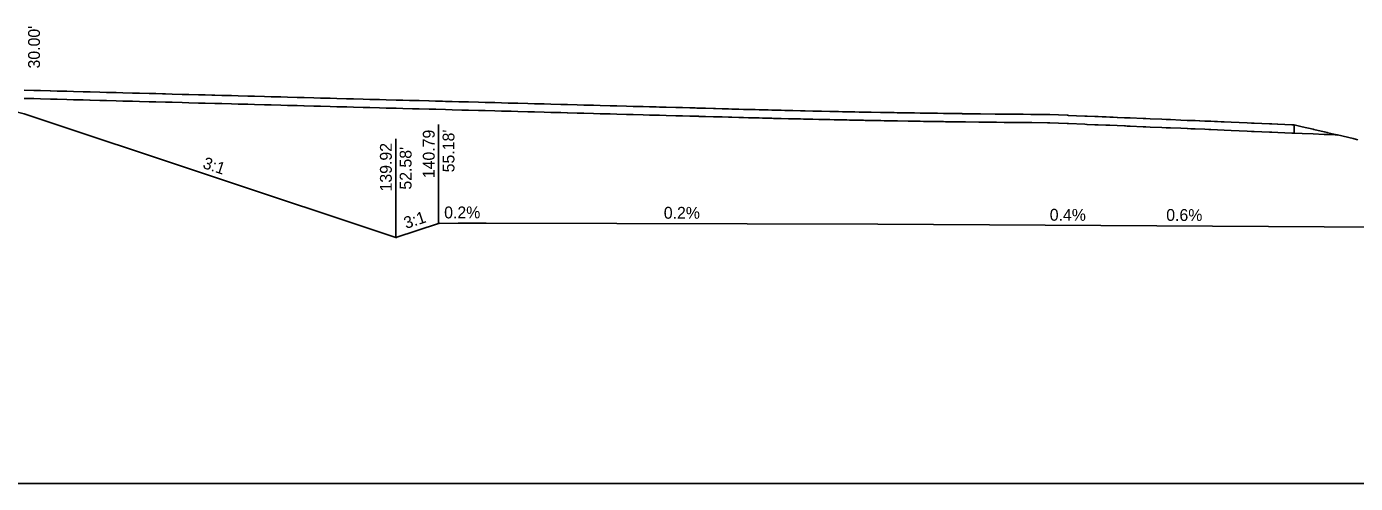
# Model space of a CAD drawing. Extents: x -26 to 4403, y -13 to 9578.
# Drawn here: x 1280.1 to 1360.9, y 8000 to 8027.7 of the extents above; entities that cross this region are included whole.
import ezdxf

# ---------------------------------------------------------------- set-up
doc = ezdxf.new("R2010")
doc.units = 0
for name, color, linetype in [('CONST_DCH', 7, 'Continuous'), ('CONST_LV3', 7, 'Continuous'), ('DTM_CORRIDOR', 7, 'Continuous'), ('DTM_P_FINISHED_GRADE', 7, 'Continuous'), ('DTM_X_GROUND', 7, 'Continuous'), ('XS_CELL', 7, 'Continuous'), ('XS_P_DR_GRAVEL', 7, 'Continuous'), ('XS_P_GROUND', 7, 'Continuous'), ('XS_P_TX_CLEARZONE', 7, 'Continuous'), ('XS_P_TX_FS_BS', 7, 'Continuous')]:
    doc.layers.add(name, color=color, linetype=linetype)

msp = doc.modelspace()

# ---------------------------------------------------------------- linework, layer by layer
at = {"layer": 'CONST_LV3'}
msp.add_lwpolyline([(1280.004, 8023.88), (1280.591, 8023.864), (1281, 8023.854), (1281.59, 8023.838), (1282, 8023.827), (1282.41, 8023.816), (1283, 8023.8), (1283.59, 8023.785), (1284, 8023.774), (1284.59, 8023.758), (1285, 8023.747), (1285.41, 8023.736), (1286, 8023.721), (1286.591, 8023.705), (1287, 8023.694), (1287.591, 8023.679), (1288, 8023.668), (1288.409, 8023.657), (1289, 8023.641), (1289.591, 8023.625), (1290, 8023.615), (1290.591, 8023.599), (1291, 8023.588), (1291.408, 8023.577), (1292, 8023.561), (1292.592, 8023.546), (1293, 8023.535), (1293.592, 8023.519), (1294, 8023.508), (1294.592, 8023.493), (1295, 8023.482), (1295.593, 8023.466), (1296, 8023.455), (1296.593, 8023.439), (1297, 8023.429), (1297.593, 8023.413), (1298, 8023.402), (1298.407, 8023.391), (1299, 8023.375), (1299.593, 8023.36), (1300, 8023.349), (1300.594, 8023.333), (1301, 8023.322), (1301.406, 8023.311), (1302, 8023.296), (1302.594, 8023.28), (1303, 8023.269), (1303.406, 8023.258), (1304, 8023.243), (1304.594, 8023.227), (1305, 8023.216), (1305.406, 8023.205), (1306, 8023.189), (1306.405, 8023.179), (1307, 8023.163), (1307.595, 8023.147), (1308, 8023.136), (1308.595, 8023.121), (1309, 8023.11), (1309.405, 8023.099), (1310, 8023.083), (1310.596, 8023.067), (1311, 8023.057), (1311.404, 8023.046), (1312, 8023.03), (1312.596, 8023.014), (1313, 8023.004), (1313.596, 8022.988), (1314, 8022.977), (1314.404, 8022.966), (1315, 8022.95), (1315.597, 8022.935), (1316, 8022.924), (1316.597, 8022.908), (1317, 8022.897), (1317.403, 8022.887), (1318, 8022.871), (1318.403, 8022.86), (1319, 8022.844), (1319.597, 8022.828), (1320, 8022.818), (1320.449, 8022.805), (1320.755, 8022.797), (1320.76, 8022.797), (1320.863, 8022.794), (1320.959, 8022.791), (1321, 8022.789), (1321.403, 8022.779), (1321.882, 8022.765), (1322, 8022.761), (1322.406, 8022.751), (1322.787, 8022.74), (1322.999, 8022.733), (1323.41, 8022.723), (1323.694, 8022.715), (1323.997, 8022.707), (1324.416, 8022.697), (1324.65, 8022.691), (1324.994, 8022.681), (1325.423, 8022.671), (1325.516, 8022.668), (1325.735, 8022.663), (1326.208, 8022.652), (1326.431, 8022.647), (1326.708, 8022.639), (1327.165, 8022.629), (1327.352, 8022.624), (1327.438, 8022.621), (1327.913, 8022.612), (1328.278, 8022.603), (1328.446, 8022.599), (1328.941, 8022.59), (1329.211, 8022.583), (1329.452, 8022.578), (1329.971, 8022.568), (1330.15, 8022.564), (1330.419, 8022.559), (1330.726, 8022.553), (1331.002, 8022.548), (1331.096, 8022.546), (1331.459, 8022.539), (1332.033, 8022.529), (1332.052, 8022.528), (1332.25, 8022.524), (1332.858, 8022.515), (1333.049, 8022.511), (1333.065, 8022.509), (1333.712, 8022.5), (1333.992, 8022.495), (1334.096, 8022.493), (1334.782, 8022.483), (1334.979, 8022.48), (1335.338, 8022.475), (1335.483, 8022.473), (1335.854, 8022.468), (1335.978, 8022.466), (1336.156, 8022.463), (1336.927, 8022.454), (1336.991, 8022.453), (1337.184, 8022.45), (1338, 8022.441), (1338.036, 8022.44), (1338.107, 8022.439), (1338.989, 8022.43), (1339.061, 8022.429), (1339.075, 8022.428), (1340.031, 8022.42), (1340.121, 8022.419), (1340.148, 8022.418), (1340.642, 8022.414), (1340.7, 8022.414), (1341.204, 8022.41), (1341.221, 8022.409), (1342.167, 8022.402), (1342.294, 8022.397), (1342.297, 8022.397), (1342.298, 8022.397), (1342.301, 8022.397), (1343.364, 8022.353), (1343.416, 8022.351), (1343.438, 8022.35), (1344.433, 8022.309), (1344.558, 8022.304), (1344.576, 8022.303), (1345.5, 8022.264), (1345.715, 8022.255), (1345.724, 8022.255), (1346.164, 8022.236), (1346.423, 8022.226), (1346.853, 8022.207), (1346.915, 8022.205), (1347.013, 8022.201), (1347.186, 8022.194), (1347.991, 8022.159), (1348.135, 8022.154), (1348.413, 8022.143), (1349.128, 8022.111), (1349.384, 8022.101), (1349.641, 8022.091), (1350.264, 8022.063), (1350.665, 8022.047), (1350.872, 8022.039), (1351.398, 8022.015), (1351.981, 8021.991), (1352.103, 8021.987), (1352.326, 8021.977), (1352.719, 8021.96), (1352.915, 8021.951), (1353.333, 8021.933), (1354.298, 8021.891), (1354.566, 8021.879), (1354.725, 8021.874), (1355.655, 8021.833), (1355.797, 8021.827), (1356.159, 8021.812), (1357.015, 8021.775), (1357.028, 8021.775), (1357.154, 8021.769)], dxfattribs=at)
at = {"layer": 'DTM_P_FINISHED_GRADE'}
msp.add_lwpolyline([(1280.004, 8023.88), (1280.591, 8023.864), (1281, 8023.854), (1281.002, 8023.854), (1281.591, 8023.838), (1282, 8023.827), (1282.002, 8023.827), (1282.591, 8023.811), (1283, 8023.8), (1283.002, 8023.8), (1283.592, 8023.785), (1284, 8023.774), (1284.002, 8023.774), (1284.592, 8023.758), (1285, 8023.747), (1285.002, 8023.747), (1285.592, 8023.732), (1286, 8023.721), (1286.002, 8023.721), (1286.592, 8023.705), (1287, 8023.694), (1287.002, 8023.694), (1287.592, 8023.678), (1288, 8023.668), (1288.002, 8023.668), (1288.593, 8023.652), (1289, 8023.641), (1289.002, 8023.641), (1289.593, 8023.625), (1290, 8023.615), (1290.002, 8023.614), (1290.593, 8023.599), (1291, 8023.588), (1291.002, 8023.588), (1291.593, 8023.572), (1292, 8023.561), (1292.002, 8023.561), (1292.593, 8023.546), (1293, 8023.535), (1293.002, 8023.535), (1293.594, 8023.519), (1294, 8023.508), (1294.002, 8023.508), (1294.594, 8023.492), (1295, 8023.482), (1295.002, 8023.482), (1295.594, 8023.466), (1296, 8023.455), (1296.002, 8023.455), (1296.594, 8023.439), (1297, 8023.429), (1297.002, 8023.429), (1297.594, 8023.413), (1298, 8023.402), (1298.002, 8023.402), (1298.595, 8023.386), (1299, 8023.375), (1299.002, 8023.375), (1299.595, 8023.36), (1300, 8023.349), (1300.002, 8023.349), (1300.595, 8023.333), (1301, 8023.322), (1301.002, 8023.322), (1301.595, 8023.306), (1302, 8023.296), (1302.002, 8023.296), (1302.595, 8023.28), (1303, 8023.269), (1303.002, 8023.269), (1303.596, 8023.253), (1304, 8023.243), (1304.002, 8023.243), (1304.596, 8023.227), (1305, 8023.216), (1305.002, 8023.216), (1305.596, 8023.2), (1306, 8023.189), (1306.002, 8023.189), (1306.596, 8023.174), (1307, 8023.163), (1307.002, 8023.163), (1307.596, 8023.147), (1308, 8023.136), (1308.002, 8023.136), (1308.597, 8023.12), (1309, 8023.11), (1309.002, 8023.11), (1309.597, 8023.094), (1310, 8023.083), (1310.002, 8023.083), (1310.597, 8023.067), (1311, 8023.057), (1311.002, 8023.057), (1311.597, 8023.041), (1312, 8023.03), (1312.002, 8023.03), (1312.598, 8023.014), (1313, 8023.004), (1313.002, 8023.003), (1313.598, 8022.988), (1314, 8022.977), (1314.002, 8022.977), (1314.598, 8022.961), (1315, 8022.95), (1315.002, 8022.95), (1315.598, 8022.934), (1316, 8022.924), (1316.002, 8022.924), (1316.598, 8022.908), (1317, 8022.897), (1317.002, 8022.897), (1317.599, 8022.881), (1318, 8022.871), (1318.002, 8022.871), (1318.599, 8022.855), (1319, 8022.844), (1319.002, 8022.844), (1319.599, 8022.828), (1320, 8022.818), (1320.002, 8022.818), (1320.45, 8022.805), (1320.755, 8022.797), (1320.76, 8022.797), (1320.863, 8022.794), (1320.959, 8022.791), (1320.961, 8022.791), (1321.002, 8022.789), (1321.403, 8022.779), (1321.882, 8022.765), (1321.883, 8022.765), (1322.001, 8022.761), (1322.406, 8022.751), (1322.787, 8022.74), (1322.789, 8022.74), (1323.001, 8022.733), (1323.41, 8022.723), (1323.694, 8022.715), (1323.696, 8022.715), (1323.999, 8022.707), (1324.416, 8022.697), (1324.65, 8022.691), (1324.651, 8022.691), (1324.864, 8022.687), (1325.209, 8022.676), (1325.423, 8022.671), (1325.516, 8022.668), (1325.517, 8022.668), (1325.99, 8022.657), (1326.431, 8022.647), (1326.433, 8022.647), (1326.71, 8022.639), (1327.165, 8022.629), (1327.352, 8022.624), (1327.354, 8022.624), (1327.44, 8022.621), (1327.913, 8022.612), (1328.278, 8022.603), (1328.28, 8022.603), (1328.447, 8022.599), (1328.941, 8022.59), (1329.211, 8022.583), (1329.212, 8022.583), (1329.469, 8022.578), (1329.71, 8022.573), (1329.971, 8022.568), (1330.15, 8022.564), (1330.152, 8022.564), (1330.458, 8022.558), (1331.002, 8022.548), (1331.096, 8022.546), (1331.099, 8022.545), (1331.461, 8022.539), (1332.033, 8022.529), (1332.052, 8022.528), (1332.054, 8022.528), (1332.252, 8022.524), (1332.858, 8022.515), (1333.05, 8022.511), (1333.052, 8022.511), (1333.067, 8022.509), (1333.712, 8022.5), (1333.992, 8022.495), (1333.995, 8022.495), (1334.099, 8022.493), (1334.435, 8022.488), (1334.636, 8022.485), (1334.979, 8022.48), (1334.982, 8022.48), (1335.129, 8022.477), (1335.854, 8022.468), (1335.978, 8022.466), (1335.981, 8022.466), (1336.159, 8022.463), (1336.927, 8022.454), (1336.991, 8022.453), (1336.994, 8022.452), (1337.187, 8022.45), (1338.001, 8022.441), (1338.036, 8022.44), (1338.039, 8022.44), (1338.111, 8022.439), (1338.989, 8022.43), (1339.061, 8022.429), (1339.065, 8022.429), (1339.078, 8022.428), (1339.544, 8022.424), (1339.651, 8022.423), (1340.121, 8022.419), (1340.125, 8022.419), (1340.152, 8022.418), (1341.165, 8022.41), (1341.204, 8022.41), (1341.208, 8022.41), (1341.225, 8022.409), (1342.167, 8022.402), (1342.294, 8022.397), (1342.297, 8022.397), (1342.298, 8022.397), (1342.302, 8022.397), (1342.305, 8022.397), (1343.364, 8022.353), (1343.417, 8022.351), (1343.42, 8022.351), (1343.442, 8022.35), (1344.433, 8022.309), (1344.558, 8022.304), (1344.562, 8022.303), (1344.58, 8022.303), (1345.057, 8022.283), (1345.248, 8022.275), (1345.715, 8022.255), (1345.724, 8022.255), (1345.727, 8022.255), (1345.965, 8022.245), (1346.853, 8022.207), (1346.915, 8022.205), (1346.919, 8022.205), (1347.017, 8022.201), (1347.189, 8022.194), (1347.991, 8022.159), (1348.135, 8022.154), (1348.138, 8022.154), (1348.416, 8022.142), (1349.128, 8022.111), (1349.384, 8022.101), (1349.387, 8022.101), (1349.644, 8022.091), (1350.264, 8022.063), (1350.665, 8022.047), (1350.668, 8022.047), (1350.874, 8022.039), (1351.148, 8022.027), (1351.738, 8022.002), (1351.981, 8021.991), (1351.983, 8021.991), (1352.105, 8021.987), (1352.505, 8021.97), (1352.915, 8021.951), (1353.333, 8021.933), (1353.335, 8021.933), (1354.299, 8021.891), (1354.566, 8021.879), (1354.725, 8021.874), (1354.726, 8021.874), (1355.655, 8021.833), (1355.797, 8021.827), (1356.159, 8021.812), (1356.159, 8021.812), (1357.015, 8021.775), (1357.028, 8021.775), (1357.154, 8021.769)], dxfattribs=at)
at = {"layer": 'DTM_X_GROUND'}
msp.add_lwpolyline([(1305.181, 8015.791), (1306.376, 8015.793), (1308.059, 8015.796), (1331.863, 8015.749), (1369.14, 8015.527), (1389.173, 8015.495), (1400, 8015.407)], dxfattribs=at)
at = {"layer": 'XS_CELL'}
msp.add_line((1250, 8000), (1400, 8000), dxfattribs=at)
at = {"layer": 'XS_P_DR_GRAVEL'}
for points in [[(1280.004, 8023.38), (1280.591, 8023.364), (1281, 8023.354), (1281.002, 8023.354), (1281.591, 8023.338), (1282, 8023.327), (1282.002, 8023.327), (1282.591, 8023.311), (1283, 8023.3), (1283.002, 8023.3), (1283.592, 8023.285), (1284, 8023.274), (1284.002, 8023.274), (1284.592, 8023.258), (1285, 8023.247), (1285.002, 8023.247), (1285.592, 8023.232), (1286, 8023.221), (1286.002, 8023.221), (1286.592, 8023.205), (1287, 8023.194), (1287.002, 8023.194), (1287.592, 8023.178), (1288, 8023.168), (1288.002, 8023.168), (1288.593, 8023.152), (1289, 8023.141), (1289.002, 8023.141), (1289.593, 8023.125), (1290, 8023.115), (1290.002, 8023.114), (1290.593, 8023.099), (1291, 8023.088), (1291.002, 8023.088), (1291.593, 8023.072), (1292, 8023.061), (1292.002, 8023.061), (1292.593, 8023.046), (1293, 8023.035), (1293.002, 8023.035), (1293.594, 8023.019), (1294, 8023.008), (1294.002, 8023.008), (1294.594, 8022.992), (1295, 8022.982), (1295.002, 8022.982), (1295.594, 8022.966), (1296, 8022.955), (1296.002, 8022.955), (1296.594, 8022.939), (1297, 8022.929), (1297.002, 8022.929), (1297.594, 8022.913), (1298, 8022.902), (1298.002, 8022.902), (1298.595, 8022.886), (1299, 8022.875), (1299.002, 8022.875), (1299.595, 8022.86), (1300, 8022.849), (1300.002, 8022.849), (1300.595, 8022.833), (1301, 8022.822), (1301.002, 8022.822), (1301.595, 8022.806), (1302, 8022.796), (1302.002, 8022.796), (1302.595, 8022.78), (1303, 8022.769), (1303.002, 8022.769), (1303.596, 8022.753), (1304, 8022.743), (1304.002, 8022.743), (1304.596, 8022.727), (1305, 8022.716), (1305.002, 8022.716), (1305.596, 8022.7), (1306, 8022.689), (1306.002, 8022.689), (1306.596, 8022.674), (1307, 8022.663), (1307.002, 8022.663), (1307.596, 8022.647), (1308, 8022.636), (1308.002, 8022.636), (1308.597, 8022.62), (1309, 8022.61), (1309.002, 8022.61), (1309.597, 8022.594), (1310, 8022.583), (1310.002, 8022.583), (1310.597, 8022.567), (1311, 8022.557), (1311.002, 8022.557), (1311.597, 8022.541), (1312, 8022.53), (1312.002, 8022.53), (1312.598, 8022.514), (1313, 8022.504), (1313.002, 8022.503), (1313.598, 8022.488), (1314, 8022.477), (1314.002, 8022.477), (1314.598, 8022.461), (1315, 8022.45), (1315.002, 8022.45), (1315.598, 8022.434), (1316, 8022.424), (1316.002, 8022.424), (1316.598, 8022.408), (1317, 8022.397), (1317.002, 8022.397), (1317.599, 8022.381), (1318, 8022.371), (1318.002, 8022.371), (1318.599, 8022.355), (1319, 8022.344), (1319.002, 8022.344), (1319.599, 8022.328), (1320, 8022.318), (1320.002, 8022.318), (1320.45, 8022.305), (1320.755, 8022.297), (1320.76, 8022.297), (1320.863, 8022.294), (1320.959, 8022.291), (1320.961, 8022.291), (1321.002, 8022.289), (1321.403, 8022.279), (1321.882, 8022.265), (1321.883, 8022.265), (1322.001, 8022.261), (1322.406, 8022.251), (1322.787, 8022.24), (1322.789, 8022.24), (1323.001, 8022.233), (1323.41, 8022.223), (1323.694, 8022.215), (1323.696, 8022.215), (1323.999, 8022.207), (1324.416, 8022.197), (1324.65, 8022.191), (1324.651, 8022.191), (1324.864, 8022.187), (1325.209, 8022.176), (1325.423, 8022.171), (1325.516, 8022.168), (1325.517, 8022.168), (1325.99, 8022.157), (1326.431, 8022.147), (1326.433, 8022.147), (1326.71, 8022.139), (1327.165, 8022.129), (1327.352, 8022.124), (1327.354, 8022.124), (1327.44, 8022.121), (1327.913, 8022.112), (1328.278, 8022.103), (1328.28, 8022.103), (1328.447, 8022.099), (1328.941, 8022.09), (1329.211, 8022.083), (1329.212, 8022.083), (1329.469, 8022.078), (1329.71, 8022.073), (1329.971, 8022.068), (1330.15, 8022.064), (1330.152, 8022.064), (1330.458, 8022.058), (1331.002, 8022.048), (1331.096, 8022.046), (1331.099, 8022.045), (1331.461, 8022.039), (1332.033, 8022.029), (1332.052, 8022.028), (1332.054, 8022.028), (1332.252, 8022.024), (1332.858, 8022.015), (1333.05, 8022.011), (1333.052, 8022.011), (1333.067, 8022.009), (1333.712, 8022), (1333.992, 8021.995), (1333.995, 8021.995), (1334.099, 8021.993), (1334.435, 8021.988), (1334.636, 8021.985), (1334.979, 8021.98), (1334.982, 8021.98), (1335.129, 8021.977), (1335.854, 8021.968), (1335.978, 8021.966), (1335.981, 8021.966), (1336.159, 8021.963), (1336.927, 8021.954), (1336.991, 8021.953), (1336.994, 8021.952), (1337.187, 8021.95), (1338.001, 8021.941), (1338.036, 8021.94), (1338.039, 8021.94), (1338.111, 8021.939), (1338.989, 8021.93), (1339.061, 8021.929), (1339.065, 8021.929), (1339.078, 8021.928), (1339.544, 8021.924), (1339.651, 8021.923), (1340.121, 8021.919), (1340.125, 8021.919), (1340.152, 8021.918), (1341.165, 8021.91), (1341.204, 8021.91), (1341.208, 8021.91), (1341.225, 8021.909), (1342.167, 8021.902), (1342.294, 8021.897), (1342.297, 8021.897), (1342.298, 8021.897), (1342.302, 8021.897), (1342.305, 8021.897), (1343.364, 8021.853), (1343.417, 8021.851), (1343.42, 8021.851), (1343.442, 8021.85), (1344.433, 8021.809), (1344.558, 8021.804), (1344.562, 8021.803), (1344.58, 8021.803), (1345.057, 8021.783), (1345.248, 8021.775), (1345.715, 8021.755), (1345.724, 8021.755), (1345.727, 8021.755), (1345.965, 8021.745), (1346.853, 8021.707), (1346.915, 8021.705), (1346.919, 8021.705), (1347.017, 8021.701), (1347.189, 8021.694), (1347.991, 8021.659), (1348.135, 8021.654), (1348.138, 8021.654), (1348.416, 8021.642), (1349.128, 8021.611), (1349.384, 8021.601), (1349.387, 8021.601), (1349.644, 8021.591), (1350.264, 8021.563), (1350.665, 8021.547), (1350.668, 8021.547), (1350.874, 8021.539), (1351.148, 8021.527), (1351.738, 8021.502), (1351.981, 8021.491), (1351.983, 8021.491), (1352.105, 8021.487), (1352.505, 8021.47), (1352.915, 8021.451), (1353.333, 8021.433), (1353.335, 8021.433), (1354.299, 8021.391), (1354.566, 8021.379), (1354.725, 8021.374), (1354.726, 8021.374), (1355.655, 8021.333), (1355.797, 8021.327), (1356.159, 8021.312), (1356.159, 8021.312), (1357.015, 8021.275), (1357.028, 8021.275), (1357.154, 8021.269), (1357.154, 8021.769), (1357.028, 8021.775), (1357.015, 8021.775), (1356.159, 8021.812), (1356.159, 8021.812), (1355.797, 8021.827), (1355.655, 8021.833), (1354.726, 8021.874), (1354.725, 8021.874), (1354.566, 8021.879), (1354.299, 8021.891), (1353.335, 8021.933), (1353.333, 8021.933), (1352.915, 8021.951), (1352.505, 8021.97), (1352.105, 8021.987), (1351.983, 8021.991), (1351.981, 8021.991), (1351.738, 8022.002), (1351.148, 8022.027), (1350.874, 8022.039), (1350.668, 8022.047), (1350.665, 8022.047), (1350.264, 8022.063), (1349.644, 8022.091), (1349.387, 8022.101), (1349.384, 8022.101), (1349.128, 8022.111), (1348.416, 8022.142), (1348.138, 8022.154), (1348.135, 8022.154), (1347.991, 8022.159), (1347.189, 8022.194), (1347.017, 8022.201), (1346.919, 8022.205), (1346.915, 8022.205), (1346.853, 8022.207), (1345.965, 8022.245), (1345.727, 8022.255), (1345.724, 8022.255), (1345.715, 8022.255), (1345.248, 8022.275), (1345.057, 8022.283), (1344.58, 8022.303), (1344.562, 8022.303), (1344.558, 8022.304), (1344.433, 8022.309), (1343.442, 8022.35), (1343.42, 8022.351), (1343.417, 8022.351), (1343.364, 8022.353), (1342.305, 8022.397), (1342.302, 8022.397), (1342.298, 8022.397), (1342.297, 8022.397), (1342.294, 8022.397), (1342.167, 8022.402), (1341.225, 8022.409), (1341.208, 8022.41), (1341.204, 8022.41), (1341.165, 8022.41), (1340.152, 8022.418), (1340.125, 8022.419), (1340.121, 8022.419), (1339.651, 8022.423), (1339.544, 8022.424), (1339.078, 8022.428), (1339.065, 8022.429), (1339.061, 8022.429), (1338.989, 8022.43), (1338.111, 8022.439), (1338.039, 8022.44), (1338.036, 8022.44), (1338.001, 8022.441), (1337.187, 8022.45), (1336.994, 8022.452), (1336.991, 8022.453), (1336.927, 8022.454), (1336.159, 8022.463), (1335.981, 8022.466), (1335.978, 8022.466), (1335.854, 8022.468), (1335.129, 8022.477), (1334.982, 8022.48), (1334.979, 8022.48), (1334.636, 8022.485), (1334.435, 8022.488), (1334.099, 8022.493), (1333.995, 8022.495), (1333.992, 8022.495), (1333.712, 8022.5), (1333.067, 8022.509), (1333.052, 8022.511), (1333.05, 8022.511), (1332.858, 8022.515), (1332.252, 8022.524), (1332.054, 8022.528), (1332.052, 8022.528), (1332.033, 8022.529), (1331.461, 8022.539), (1331.099, 8022.545), (1331.096, 8022.546), (1331.002, 8022.548), (1330.458, 8022.558), (1330.152, 8022.564), (1330.15, 8022.564), (1329.971, 8022.568), (1329.71, 8022.573), (1329.469, 8022.578), (1329.212, 8022.583), (1329.211, 8022.583), (1328.941, 8022.59), (1328.447, 8022.599), (1328.28, 8022.603), (1328.278, 8022.603), (1327.913, 8022.612), (1327.44, 8022.621), (1327.354, 8022.624), (1327.352, 8022.624), (1327.165, 8022.629), (1326.71, 8022.639), (1326.433, 8022.647), (1326.431, 8022.647), (1325.99, 8022.657), (1325.517, 8022.668), (1325.516, 8022.668), (1325.423, 8022.671), (1325.209, 8022.676), (1324.864, 8022.687), (1324.651, 8022.691), (1324.65, 8022.691), (1324.416, 8022.697), (1323.999, 8022.707), (1323.696, 8022.715), (1323.694, 8022.715), (1323.41, 8022.723), (1323.001, 8022.733), (1322.789, 8022.74), (1322.787, 8022.74), (1322.406, 8022.751), (1322.001, 8022.761), (1321.883, 8022.765), (1321.882, 8022.765), (1321.403, 8022.779), (1321.002, 8022.789), (1320.961, 8022.791), (1320.959, 8022.791), (1320.863, 8022.794), (1320.76, 8022.797), (1320.755, 8022.797), (1320.45, 8022.805), (1320.002, 8022.818), (1320, 8022.818), (1319.599, 8022.828), (1319.002, 8022.844), (1319, 8022.844), (1318.599, 8022.855), (1318.002, 8022.871), (1318, 8022.871), (1317.599, 8022.881), (1317.002, 8022.897), (1317, 8022.897), (1316.598, 8022.908), (1316.002, 8022.924), (1316, 8022.924), (1315.598, 8022.934), (1315.002, 8022.95), (1315, 8022.95), (1314.598, 8022.961), (1314.002, 8022.977), (1314, 8022.977), (1313.598, 8022.988), (1313.002, 8023.003), (1313, 8023.004), (1312.598, 8023.014), (1312.002, 8023.03), (1312, 8023.03), (1311.597, 8023.041), (1311.002, 8023.057), (1311, 8023.057), (1310.597, 8023.067), (1310.002, 8023.083), (1310, 8023.083), (1309.597, 8023.094), (1309.002, 8023.11), (1309, 8023.11), (1308.597, 8023.12), (1308.002, 8023.136), (1308, 8023.136), (1307.596, 8023.147), (1307.002, 8023.163), (1307, 8023.163), (1306.596, 8023.174), (1306.002, 8023.189), (1306, 8023.189), (1305.596, 8023.2), (1305.002, 8023.216), (1305, 8023.216), (1304.596, 8023.227), (1304.002, 8023.243), (1304, 8023.243), (1303.596, 8023.253), (1303.002, 8023.269), (1303, 8023.269), (1302.595, 8023.28), (1302.002, 8023.296), (1302, 8023.296), (1301.595, 8023.306), (1301.002, 8023.322), (1301, 8023.322), (1300.595, 8023.333), (1300.002, 8023.349), (1300, 8023.349), (1299.595, 8023.36), (1299.002, 8023.375), (1299, 8023.375), (1298.595, 8023.386), (1298.002, 8023.402), (1298, 8023.402), (1297.594, 8023.413), (1297.002, 8023.429), (1297, 8023.429), (1296.594, 8023.439), (1296.002, 8023.455), (1296, 8023.455), (1295.594, 8023.466), (1295.002, 8023.482), (1295, 8023.482), (1294.594, 8023.492), (1294.002, 8023.508), (1294, 8023.508), (1293.594, 8023.519), (1293.002, 8023.535), (1293, 8023.535), (1292.593, 8023.546), (1292.002, 8023.561), (1292, 8023.561), (1291.593, 8023.572), (1291.002, 8023.588), (1291, 8023.588), (1290.593, 8023.599), (1290.002, 8023.614), (1290, 8023.615), (1289.593, 8023.625), (1289.002, 8023.641), (1289, 8023.641), (1288.593, 8023.652), (1288.002, 8023.668), (1288, 8023.668), (1287.592, 8023.678), (1287.002, 8023.694), (1287, 8023.694), (1286.592, 8023.705), (1286.002, 8023.721), (1286, 8023.721), (1285.592, 8023.732), (1285.002, 8023.747), (1285, 8023.747), (1284.592, 8023.758), (1284.002, 8023.774), (1284, 8023.774), (1283.592, 8023.785), (1283.002, 8023.8), (1283, 8023.8), (1282.591, 8023.811), (1282.002, 8023.827), (1282, 8023.827), (1281.591, 8023.838), (1281.002, 8023.854), (1281, 8023.854), (1280.591, 8023.864), (1280.004, 8023.88)], [(1357.154, 8021.269), (1357.639, 8021.249), (1358.32, 8021.22), (1358.982, 8021.191), (1359.167, 8021.183), (1359.654, 8021.163), (1359.818, 8021.156)]]:
    msp.add_lwpolyline(points, dxfattribs=at)
at = {"layer": 'XS_P_GROUND'}
for points in [[(1302.576, 8014.923), (1302.576, 8014.923), (1280, 8022.447), (1280, 8022.447), (1272.759, 8024.258)], [(1357.154, 8021.769), (1357.639, 8021.66), (1357.654, 8021.656), (1358.32, 8021.504), (1358.355, 8021.496), (1358.982, 8021.351), (1358.997, 8021.347), (1359.167, 8021.308), (1359.212, 8021.298), (1359.654, 8021.195), (1359.781, 8021.165), (1360.749, 8020.936), (1360.794, 8020.926), (1361.029, 8020.871)], [(1302.576, 8014.923), (1305.181, 8015.791)]]:
    msp.add_lwpolyline(points, dxfattribs=at)
at = {"layer": 'XS_P_TX_CLEARZONE'}
for p, q in [((1305.181, 8015.791), (1305.181, 8021.791)), ((1302.576, 8014.923), (1302.576, 8020.923))]:
    msp.add_line(p, q, dxfattribs=at)

# ---------------------------------------------------------------- texts
at = {"layer": 'CONST_DCH'}
msp.add_text('X', height=0.12, dxfattribs=at).set_placement((1302.537, 8014.863))
at = {"layer": 'DTM_CORRIDOR'}
msp.add_text('X', height=0.12, dxfattribs=at).set_placement((1305.142, 8015.731))
at = {"layer": 'XS_P_TX_CLEARZONE'}
for s, p in [("30.00'", (1280.96, 8025.195)), ('140.79', (1304.941, 8018.533)), ("55.18'", (1306.141, 8018.89)), ('139.92', (1302.336, 8017.727)), ("52.58'", (1303.536, 8017.84))]:
    msp.add_text(s, height=0.72, rotation=90, dxfattribs=at).set_placement(p)
at = {"layer": 'XS_P_TX_FS_BS'}
for s, rotation, p in [('3:1', 341.56677, (1290.802, 8019.163)), ('0.2%', 0.09516, (1305.518, 8016.092)), ('0.2%', 0.09516, (1305.518, 8016.092)), ('0.2%', 359.88631, (1318.86, 8016.074)), ('0.2%', 359.88631, (1318.86, 8016.074)), ('3:1', 18.43493, (1303.203, 8015.448)), ('0.4%', 359.78699, (1342.308, 8015.953)), ('0.6%', 359.65896, (1349.385, 8015.944)), ('0.6%', 359.65896, (1349.385, 8015.944))]:
    msp.add_text(s, height=0.72, rotation=rotation, dxfattribs=at).set_placement(p)

doc.saveas('drawing.dxf')
